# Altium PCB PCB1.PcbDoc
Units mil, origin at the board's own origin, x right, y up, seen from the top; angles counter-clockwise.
Board outline 794 x 1228 mil, 2 copper layers (Top Layer, Bottom Layer); 31 components, 47 nets, 231 pads, 76 vias.
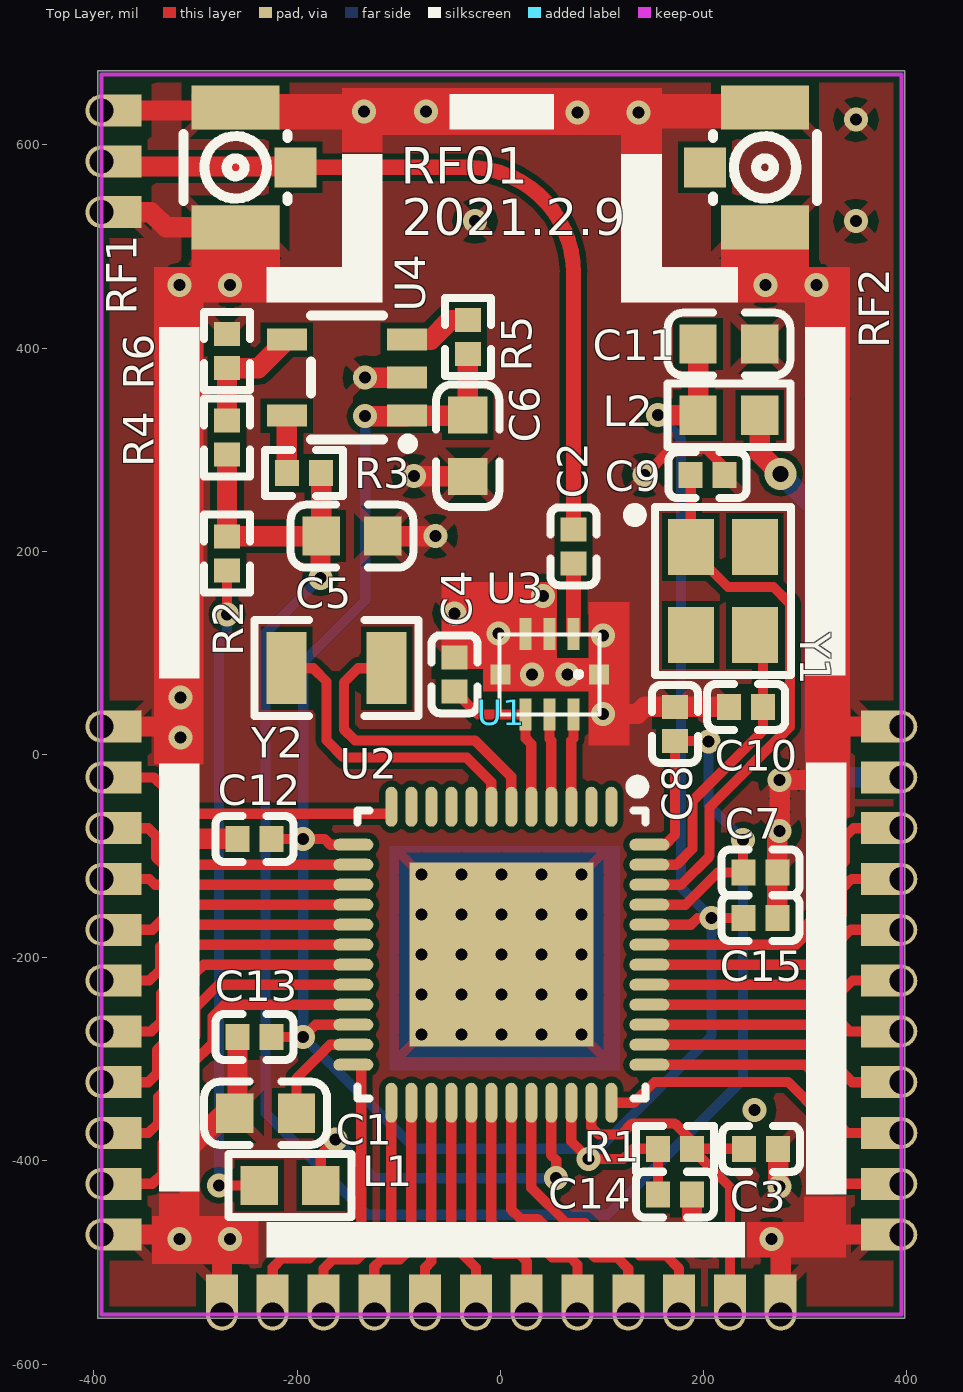
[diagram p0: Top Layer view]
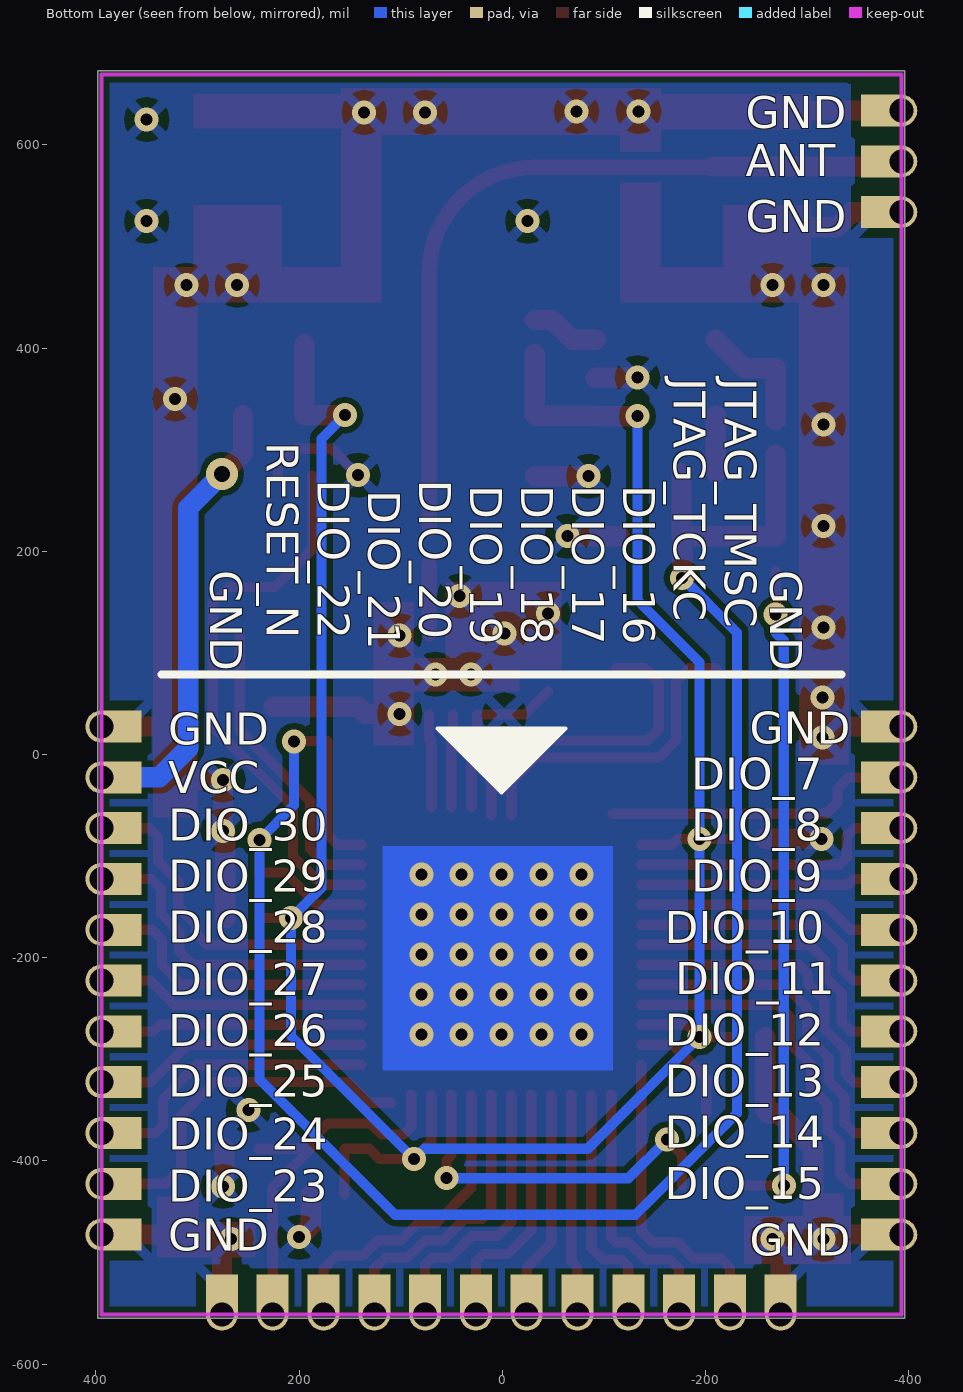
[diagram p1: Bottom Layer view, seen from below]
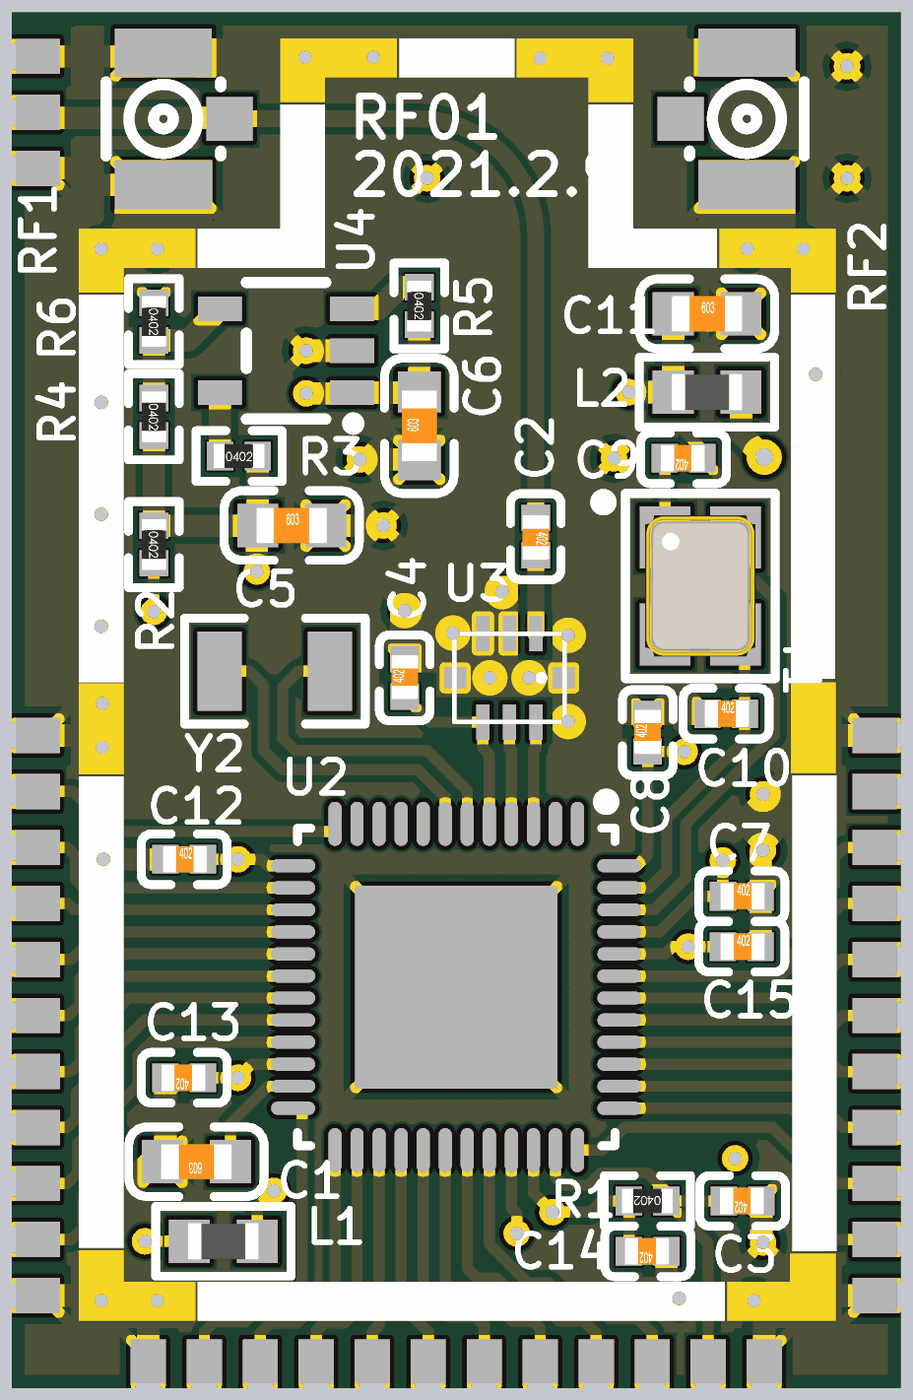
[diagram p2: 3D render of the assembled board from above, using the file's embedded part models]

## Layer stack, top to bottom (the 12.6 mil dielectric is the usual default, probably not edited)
Top Solder: solder mask 0.4, Solder Resist, Dk 3.5
Top Layer: signal copper 1.4
Dielectric 1: dielectric 12.6, FR-4, Dk 4.8
Bottom Layer: signal copper 1.4
Bottom Solder: solder mask 0.4, Solder Resist, Dk 3.5

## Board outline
-396,673 398,673 398,-555 -396,-555

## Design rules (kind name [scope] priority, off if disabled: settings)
Clearance [All] p1: gap=6
ComponentClearance [All] p1: gap=0 collisioncheckmode=3 verticalgap=0 showdistances=FALSE
PolygonConnect [All] p1: connectstyle=Relief reliefconductorwidth=10 reliefentries=4 polygonreliefangle="45 Angle" airgapwidth=10
RoutingVias [All] p1: holewidth=28 width=50 viastyle="Through Hole" minholewidth=1 minwidth=2 maxholewidth=28 maxwidth=50
SMDNeckDown [All] p1: percent=50.000
SolderMaskExpansion [All] p1: expansion=4
Width [All] p1: maxlimit=100 minlimit=10 preferedwidth=10 minimp=50.000000 maximp=50.000000 favimp=50.000000
29 further rules are at their usual default settings.

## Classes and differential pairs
component class Sheet2: U1

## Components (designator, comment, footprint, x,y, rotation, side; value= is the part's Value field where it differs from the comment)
C1 "1uF (105) 10% 50V" 0603_C -231,-353 r180 top
C2 "330pF (331) 5% 50V" 0402_C 72,205 r270 top
C3 "100nF (104) 10% 16V" 0402_C 256.73,-388 r180 top
C4 "330pF (331) 5% 50V" 0402_C -45,79 r90 top
C5 "22uF (226) 20% 6.3V" 0603_C -146,215 r0 top
C6 "1uF (105) 10% 50V" 0603_C -32,304 r90 top
C7 "100nF (104) 10% 16V" 0402_C 256,-116 r0 top
C8 "100nF (104) 10% 16V" 0402_C 172,30 r90 top
C9 "6.8pF (6R8) 0.25pF 50V" 0402_C 204,275 r180 top
C10 "6.8pF (6R8) 0.25pF 50V" 0402_C 242,47 r0 top
C11 "22uF (226) 20% 6.3V" 0603_C 225,404 r0 top
C12 "100nF (104) 10% 16V" 0402_C -242,-83 r0 top
C13 "100nF (104) 10% 16V" 0402_C -242,-278 r180 top
C14 "100nF (104) 10% 16V" 0402_C 172,-433 r180 top
C15 "100nF (104) 10% 16V" 0402_C 256,-161 r0 top
L1 "6.8uH ±10%" 0603_L -207,-424 r0 top
L2 "10uH ±10%" 0603_L 225,334 r180 top
R1 "100KΩ (1003) ±1%" 0402_R 171.73,-388 r180 top
R2 "0Ω (0R0) ±1%" 0402_R -269,198 r270 top
R3 "0Ω (0R0) ±1%" 0402_R -193,277 r0 top
R4 "22KΩ (2202) ±1%" 0402_R -269,312 r270 top
R5 "10KΩ (1002) ±1%" 0402_R -32,411 r270 top
R6 "20KΩ (2002) ±1%" 0402_R -269,397 r270 top
RF1 "KH-IPEX-K501-29" ANT-SMD_KH-IPEX-K501-29 -231,578 r270 top
RF2 "KH-IPEX-K501-29" ANT-SMD_KH-IPEX-K501-29 231,578 r90 top
U1 "E79-400DM2005S" E79-400DM2005S_V1.0_MODULE -16,0 r0 top locked
U2 "CC1352R1F3RGZR" QFN48 1,-197 r270 top locked
U3 "RFBLN2520090YC3T10" FILTER-SMD_8P-L2.5-W2.0-BL 48.5,79 r0 top locked
U4 "SGM2036-ADJYN5G/TR" SOT-23-5_L3.0-W1.7-P0.95-LS2.8-BR -151,371 r0 top
Y1 "48MHZ 20PF 10PPM" SMD-3225_4P 219,161 r270 top
Y2 "32.768KHz ±20ppm 12.5pF" "SMD-3215_2P FC - 135" -161,85 r0 top

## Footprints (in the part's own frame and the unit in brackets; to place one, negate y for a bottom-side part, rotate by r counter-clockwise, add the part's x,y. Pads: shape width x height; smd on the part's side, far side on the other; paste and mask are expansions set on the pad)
0402_C [mm]
  rect 0.6x0.65 smd mask+0.051: 1(-0.425,0) 2(0.425,0)
  silkscreen extent -0.97,-0.58 0.97,0.58, body extent -0.48,-0.3 0.52,0.3, height 0.2
0402_R [mm]
  rect 0.6x0.65 smd mask+0.051: 1(-0.425,0) 2(0.425,0)
  silkscreen extent -0.97,-0.58 0.97,0.58, body extent -0.57,-0.27 0.58,0.28, height 0.41
0603_C [mm]
  rect 0.93x0.98 smd: 1(-0.77,0) 2(0.77,0)
  silkscreen extent -1.53,-0.79 1.54,0.79, body extent -0.8,-0.4 0.8,0.4, height 0.3
0603_L [mm]
  rect 0.93x0.98 smd: 1(-0.77,0) 2(0.77,0)
  silkscreen extent -1.53,-0.79 1.54,0.79, body extent -0.82,-0.41 0.83,0.41, height 0.46
ANT-SMD_KH-IPEX-K501-29 [mm]
  rect 1.1x2.2 smd: 1(-1.5,-0.75) 3(1.5,-0.75)
  rect 1x1.05 smd: 2(0,0.75)
  silkscreen extent -0.84,-2.05 0.84,0.55
E79-400DM2005S_V1.0_MODULE [mm]
  round 0.8 hole 0.6: 1(-9.568,16.1) 2(-9.568,14.83) 3(-9.568,13.56) 4(-9.568,0.7) 5(-9.568,-0.57) 6(-9.568,-1.84) 7(-9.568,-3.11) 8(-9.568,-4.38) 9(-9.568,-5.65) 10(-9.568,-6.92) 11(-9.568,-8.19) 12(-9.568,-9.46) 13(-9.568,-10.73) 14(-9.568,-12) 15(-6.553,-14) 16(-5.283,-14) 17(-4.013,-14) 18(-2.743,-14) 19(-1.473,-14) 20(-0.203,-14) 21(1.067,-14) 22(2.337,-14) 23(3.607,-14) 24(4.877,-14) 25(6.147,-14) 26(7.417,-14) 27(10.432,-12) 28(10.432,-10.73) 29(10.432,-9.46) 30(10.432,-8.19) 31(10.432,-6.92) 32(10.432,-5.65) 33(10.432,-4.38) 34(10.432,-3.11) 35(10.432,-1.84) 36(10.432,-0.57) 37(10.432,0.7)
  rect 1x0.8 smd: 1(-9.06,16.1) 2(-9.06,14.83) 3(-9.06,13.56) 4(-9.06,0.7) 5(-9.06,-0.57) 6(-9.06,-1.84) 7(-9.06,-3.11) 8(-9.06,-4.38) 9(-9.06,-5.65) 10(-9.06,-6.92) 11(-9.06,-8.19) 12(-9.06,-9.46) 13(-9.06,-10.73) 14(-9.06,-12) 27(9.924,-12) 28(9.924,-10.73) 29(9.924,-9.46) 30(9.924,-8.19) 31(9.924,-6.92) 32(9.924,-5.65) 33(9.924,-4.38) 34(9.924,-3.11) 35(9.924,-1.84) 36(9.924,-0.57) 37(9.924,0.7)
  rect 1x0.8 smd far side: 1(-9.06,16.1) 2(-9.06,14.83) 3(-9.06,13.56) 4(-9.06,0.7) 5(-9.06,-0.57) 6(-9.06,-1.84) 7(-9.06,-3.11) 8(-9.06,-4.38) 9(-9.06,-5.65) 10(-9.06,-6.92) 11(-9.06,-8.19) 12(-9.06,-9.46) 13(-9.06,-10.73) 14(-9.06,-12) 27(9.924,-12) 28(9.924,-10.73) 29(9.924,-9.46) 30(9.924,-8.19) 31(9.924,-6.92) 32(9.924,-5.65) 33(9.924,-4.38) 34(9.924,-3.11) 35(9.924,-1.84) 36(9.924,-0.57) 37(9.924,0.7)
  rect 0.8x1 smd: 15(-6.553,-13.492) 16(-5.283,-13.492) 17(-4.013,-13.492) 18(-2.743,-13.492) 19(-1.473,-13.492) 20(-0.203,-13.492) 21(1.067,-13.492) 22(2.337,-13.492) 23(3.607,-13.492) 24(4.877,-13.492) 25(6.147,-13.492) 26(7.417,-13.492)
  rect 0.8x1 smd far side: 15(-6.553,-13.492) 16(-5.283,-13.492) 17(-4.013,-13.492) 18(-2.743,-13.492) 19(-1.473,-13.492) 20(-0.203,-13.492) 21(1.067,-13.492) 22(2.337,-13.492) 23(3.607,-13.492) 24(4.877,-13.492) 25(6.147,-13.492) 26(7.417,-13.492)
  Keep-Out Layer lines w0.1: -9.568,-14 -9.568,17 10.432,17 10.432,-14 -9.568,-14
FILTER-SMD_8P-L2.5-W2.0-BL [mm]
  rect 0.3x0.8 smd: 1(0.6,1.006) 2(0,1.006) 3(-0.6,1.006) 5(-0.6,-1.006) 6(0,-1.006) 7(0.6,-1.006)
  rect 0.5x0.5 smd: 4(-1.233,0) 8(1.233,0)
  silkscreen extent -1.25,-1 1.25,1
QFN48 [mm]
  rect 4.6x4.6 smd: 0(0,0)
  oval 1x0.3 smd: 1(-3.7,2.75) 2(-3.7,2.25) 3(-3.7,1.75) 4(-3.7,1.25) 5(-3.7,0.75) 6(-3.7,0.25) 7(-3.7,-0.25) 8(-3.7,-0.75) 9(-3.7,-1.25) 10(-3.7,-1.75) 11(-3.7,-2.25) 12(-3.7,-2.75) 25(3.7,-2.75) 26(3.7,-2.25) 27(3.7,-1.75) 28(3.7,-1.25) 29(3.7,-0.75) 30(3.7,-0.25) 31(3.7,0.25) 32(3.7,0.75) 33(3.7,1.25) 34(3.7,1.75) 35(3.7,2.25) 36(3.7,2.75)
  oval 0.3x1 smd: 13(-2.75,-3.7) 14(-2.25,-3.7) 15(-1.75,-3.7) 16(-1.25,-3.7) 17(-0.75,-3.7) 18(-0.25,-3.7) 19(0.25,-3.7) 20(0.75,-3.7) 21(1.25,-3.7) 22(1.75,-3.7) 23(2.25,-3.7) 24(2.75,-3.7) 37(2.75,3.7) 38(2.25,3.7) 39(1.75,3.7) 40(1.25,3.7) 41(0.75,3.7) 42(0.25,3.7) 43(-0.25,3.7) 44(-0.75,3.7) 45(-1.25,3.7) 46(-1.75,3.7) 47(-2.25,3.7) 48(-2.75,3.7)
  silkscreen extent -4.35,-3.6 3.6,3.6
"SMD-3215_2P FC - 135" [mm]
  rect 1x1.8 smd: 1(-1.25,0) 2(1.25,0)
  silkscreen extent -2.05,-1.2 2.05,1.2
SMD-3225_4P [mm]
  rect 1.4x1.15 smd: 1(-1.1,-0.8) 2(1.1,-0.8) 3(1.1,0.8) 4(-1.1,0.8)
  silkscreen extent -2.1,-2.35 2.1,1.7, body extent -1.6,-1.25 1.6,1.25, height 0.61
SOT-23-5_L3.0-W1.7-P0.95-LS2.8-BR [mm]
  rect 1x0.55 smd: 1(1.5,-0.95) 2(1.5,0) 3(1.5,0.95) 4(-1.5,0.95) 5(-1.5,-0.95)
  silkscreen extent -0.9,-1.78 1.65,1.55

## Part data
C1 C6: library part "0603 1uF (105) 10% 50V", "贴片电容"
C2 C4: library part "0402 330pF (331) 5% 50V", "贴片电容"
C3 C7 C8 C12 C13 C14 C15: library part "0402 100nF (104) 10% 16V", "贴片电容"
C5 C11: library part "0603 22uF (226) 20% 6.3V", "贴片电容"
C9 C10: library part "0402 6.8pF (6R8) 0.25pF 50V", "贴片电容"
L1: library part "0603 4.7uH 10%", "贴片电感"
L2: library part "0603 10uH 10%", "贴片电感"
R1: library part "0402 100KΩ (1003) 1%", "贴片电阻"
R2 R3: library part "0402 0Ω (0R0) 1%", "贴片电阻"
R4: library part "0402 22KΩ (2202) 1%", "贴片电阻"
R5: library part "0402 10KΩ (1002) 1%", "贴片电阻"
R6: library part "0402 20KΩ (2002) 1%", "贴片电阻"
Y1: library part "SMD-3225_4P  12MHZ 20PF 10PPM", "贴片晶振"
Y2: library part "SMD-3215_2P 32.768KHz 20ppm 12.5pF", "贴片晶振"

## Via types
v1: diameter 23.62, hole 11.81, Top Layer to Bottom Layer, 75 vias
v2: diameter 31.5, hole 15.75, Top Layer to Bottom Layer, 1 vias

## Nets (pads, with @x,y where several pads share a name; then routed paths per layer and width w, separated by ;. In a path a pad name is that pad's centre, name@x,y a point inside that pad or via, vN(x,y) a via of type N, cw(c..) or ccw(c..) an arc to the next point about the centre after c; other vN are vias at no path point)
2.4G_ANT: RF2.2
3V3: L2.1 U1.36 | length 427.7
  Top Layer w20: L2.1 255.31,296.69 v2(276,276)
  Bottom Layer w20: v2(276,276) 309,243 309,6 337.44,-22.44 U1.36@374.7,-22.44
433M_ANT: C2.1 RF1.2 U1.2 | length 750.5
  Top Layer w15: RF1.2 -32,578 cw(c-32,474) 72,474 C2.1
  Top Layer w20: U1.2@-372.7,578.86 RF1.2@-207.33,578.86
DIO7: U1.5 U2.12 | length 287.2
  Top Layer w10: U1.5@-372.7,-22.44 -341,-22.44 -330,-33.44 -330,-47 -318.8,-58.2 U2.12@-108.27,-58.2
DIO8: U1.6 U2.14 | length 263.1
  Top Layer w10: U1.6@-372.7,-72.44 -346.56,-72.44 -339,-80 -339,-101 -331.58,-108.42 U2.14@-136.79,-108.42
DIO9: U1.7 U2.15 | length 238.2
  Top Layer w10: U1.7@-372.7,-122.44 -345.56,-122.44 -339.9,-128.1 U2.15@-136.79,-128.1
DIO10: U1.8 U2.16 | length 246.1
  Top Layer w10: U1.8@-372.7,-172.44 -342.44,-172.44 -317.79,-147.79 U2.16@-136.79,-147.79
DIO11: U1.9 U2.17 | length 272.1
  Top Layer w10: U1.9@-372.7,-222.44 -345.44,-222.44 -335,-212 -335,-189.04 -313.43,-167.47 U2.17@-136.79,-167.47
DIO12: U1.10 U2.18 | length 297
  Top Layer w10: U1.10@-372.7,-272.44 -343.44,-272.44 -334,-263 -334,-235.04 -318,-219.04 -318,-203 -302.16,-187.16 U2.18@-136.79,-187.16
DIO13: U1.11 U2.19 | length 319.5
  Top Layer w10: U1.11@-372.7,-322.44 -346.44,-322.44 -338,-314 -338,-291.04 -317,-270.04 -317,-242.08 -301,-226.08 -301,-216 -291.84,-206.84 U2.19@-136.79,-206.84
DIO14: U1.12 U2.20 | length 341.4
  Top Layer w10: U1.12@-372.7,-372.44 -346.4,-372.44 -337,-363.04 -337,-337.04 -321,-321.04 -321,-298.08 -300,-277.08 -300,-249.12 -277.4,-226.53 U2.20@-136.79,-226.53
DIO15: U1.13 U2.21 | length 370.4
  Top Layer w10: U1.13@-372.7,-422.44 -342.44,-422.44 -332.46,-412.46 -332.46,-382.54 -320,-370.08 -320,-344.08 -304,-328.08 -304,-305.12 -283,-284.12 -283,-258 -271.21,-246.21 U2.21@-136.79,-246.21
DIO16: U1.18 U2.26 | length 222
  Top Layer w10: U1.18@-124,-531.18 -124,-504 -117,-497 -99,-497 -87.58,-485.58 U2.26@-87.58,-334.79
DIO17: U1.19 U2.27 | length 198.9
  Top Layer w10: U1.19@-74,-531.18 -74,-505 -67.9,-498.9 U2.27@-67.9,-334.79
DIO18: U1.20 U2.28 | length 206.4
  Top Layer w10: U2.28@-48.21,-334.79 -48.21,-480.79 -24,-505 U1.20@-24,-531.18
DIO19: U1.21 U2.29 | length 233
  Top Layer w10: U2.29@-28.53,-334.79 -28.53,-468.47 -5.5,-491.5 18.5,-491.5 26,-499 U1.21@26,-531.18
DIO20: U1.22 U2.30 | length 256.7
  Top Layer w10: U2.30@-8.84,-334.79 -8.84,-460.16 5,-474 30.04,-474 51.04,-495 69,-495 76,-502 U1.22@76,-531.18
DIO21: U1.23 U2.31 | length 277.5
  Top Layer w10: U2.31@10.84,-334.79 10.84,-447.84 20,-457 37.08,-457 58.08,-478 76.04,-478 93.04,-495 115,-495 126,-506 U1.23@126,-531.18
DIO22: U1.24 U2.32 | length 295.2
  Top Layer w10: U2.32@30.53,-334.79 30.53,-426.4 65.12,-461 83.08,-461 100.08,-478 122.04,-478 137.04,-493 163,-493 176,-506 U1.24@176,-531.18
DIO23: U1.28 U2.36 | length 345.8
  Top Layer w10: U2.36 131.33,-342.67 151.73,-322.27 283.27,-322.27 316,-355 316,-407 331.44,-422.44 U1.28@374.7,-422.44
DIO24: U1.29 U2.37 | length 279
  Top Layer w10: U2.37@138.8,-305.27 300.27,-305.27 334,-339 334,-365 341.44,-372.44 U1.29@374.7,-372.44
DIO25: U1.30 U2.38 | length 251.2
  Top Layer w10: U2.38@138.8,-285.58 309.58,-285.58 346.44,-322.44 U1.30@374.7,-322.44
DIO26: U1.31 U2.39 | length 238.6
  Top Layer w10: U2.39@138.8,-265.9 336.9,-265.9 343.44,-272.44 U1.31@374.7,-272.44
DIO27: U1.32 U2.40 | length 245.8
  Top Layer w10: U2.40@138.8,-246.21 322.79,-246.21 346.56,-222.44 U1.32@374.7,-222.44
DIO28: U1.33 U2.41 | length 273
  Top Layer w10: U2.41@138.8,-226.53 315.47,-226.53 335,-207 335,-182 344.56,-172.44 U1.33@374.7,-172.44
DIO29: U1.34 U2.42 | length 296.6
  Top Layer w10: U2.42@138.8,-206.84 305.16,-206.84 318,-194 318,-174.96 336,-156.96 336,-132 345.56,-122.44 U1.34@374.7,-122.44
DIO30: U1.35 U2.43 | length 317.4
  Top Layer w10: U2.43@138.8,-187.16 290.84,-187.16 301,-177 301,-167.92 319,-149.92 319,-124.96 339,-104.96 339,-81 347.56,-72.44 U1.35@374.7,-72.44
GND: C1.2 C3.1 C4.2 C5.2 C6.1 C7.2 C8.2 C9.1 C10.1 C11.2 C12.1 C13.2 C14.1 C15.2 R6.1 RF1.1 RF1.3 RF2.1 RF2.3 U1.1 U1.3 U1.4 U1.14 U1.15 U1.26 U1.27 U1.37 U2.0 U3.2 U3.3 U3.4 U3.8 U4.2 | length 1463.1
  Top Layer w10: v1(142,275) 168,301 202.51,301 220.73,282.78 C9.1
  Top Layer w20: U1.14@-372.7,-472.44 -302.56,-472.44 ; U1.4@-372.7,27.56 -325.56,27.56 ; U1.3@-372.7,533.86 -343.86,533.86 -328.95,518.94 RF1.3 ; U1.1@-372.7,633.86 RF1.1@-263.72,633.86 ; v1(-314,-83) C12.1 ; -306,-445 -306,-387 -272,-353 C1.2 ; U1.15@-274,-531.18 v1@-274,-475 ; C1.2@-258.73,-350.42 C13.2 ; v1(-133,371) U4.2 ; C5.2 v1(-64,215) ; v1(-85,274) C6.1@-32.32,274 ; v1(101,40) 135,40 142,47 C10.1 ; C14.1 188.73,-463.73 v1(200,-475) ; C15.2 C7.2 v1@272.73,-77.27 ; v1@273.46,-423.46 C3.1 ; v1(275,-75) v1(275,-25) 325,-25 ; U1.26@276,-531.18 276,-486 ; 300.56,-472.44 U1.27@374.7,-472.44 ; 319.44,27.56 U1.37@374.7,27.56
  other v1: -316,-477 -266,-477 267,-477 275,-425 250,-350 -77.74,-275.74 -38.37,-275.74 1,-275.74 40.37,-275.74 79.74,-275.74 -77.74,-236.37 -38.37,-236.37 1,-236.37 40.37,-236.37 79.74,-236.37 -77.74,-197 -38.37,-197 1,-197 40.37,-197 79.74,-197 -77.74,-157.63 -38.37,-157.63 1,-157.63 40.37,-157.63 79.74,-157.63 -77.74,-118.26 -38.37,-118.26 1,-118.26 40.37,-118.26 79.74,-118.26 -315,17 -315,56 31,79 66,79 101,117 -2,119 -316,125 -45,139 42,156 -316,225 -316,325 322,350 -316,462 -266,462 261,462 311,462 -25,525 350,525 350,625 76,632 136,632 -134,633 -73,633
NetC1_1: C1.1 U2.23 | length 111.9
  Top Layer w10: C1.1 -200.68,-318.68 -167.58,-285.58 U2.23@-136.79,-285.58
NetC2_2: C2.2 U3.1 | length 69.5
  Top Layer w15: U3.1 C2.2@72.12,188.15
NetC4_1: C4.1 U2.5 U3.5 | length 172.4
  Top Layer w10: C4.1 -22.12,39.39 U3.5 24.88,16.12 30.53,10.47 U2.5
NetC9_2: C9.2 U2.46 Y1.1 | length 553
  Top Layer w10: U2.46@138.8,-128.1 177.86,-128.1 206,-99.96 206,-51.63 285,27.37 285,148.94 268.94,165 224.05,165 187.5,201.55 Y1.1 C9.2@187.5,274.76
NetC10_2: C10.2 U2.47 Y1.3 | length 296
  Top Layer w10: U2.47@138.8,-108.42 173.5,-108.42 189,-92.92 189,-46 258.5,23.5 Y1.3@258.5,117.69
NetL1_1: L1.1 R2.2 | length 648.3
  Top Layer w10: v1(-277,-424) L1.1 ; v1(-269,138) R2.2
  Bottom Layer w10: v1(-277,-424) -277,112 -269,120 v1(-269,138)
NetL1_2: L1.2 U2.33 | length 368
  Top Layer w10: L1.2 -176.68,-393.68 v1(-162,-379) ; U2.33@50.21,-334.79 50.21,-394.21 55,-399 v1(55,-417)
  Bottom Layer w10: v1(-162,-379) -124,-417 v1(55,-417)
NetR3_1: R3.1 U4.5 | length 56.3
  Top Layer w20: R3.1@-210.06,277.33 U4.5
NetR4_1: R4.1 R6.2 U4.4 | length 122.1
  Top Layer w20: R4.1 R6.2 -238.19,380.27 U4.4
NetR5_1: R5.1 U4.3 | length 68
  Top Layer w20: U4.3 -68.6,408.4 -49.27,427.73 R5.1
NetU2_3: U2.3 U3.7 | length 88.5
  Top Layer w10: U2.3 69.9,13.9 ; 72.12,16.12 U3.7
NetU2_4: U2.4 U3.6 | length 91.4
  Top Layer w10: U3.6 48.5,15.5 50.21,13.79 U2.4
NetU2_6: U2.6 Y2.2 | length 315.6
  Top Layer w10: Y2.2 -140,85 -154,71 -154,25 -143,14 -25,14 10.84,-21.84 U2.6@10.84,-59.2
NetU2_7: U2.7 Y2.1 | length 313.8
  Top Layer w10: Y2.1 -184,85 -171,72 -171,14 -154,-3 -33,-3 -8.84,-27.16 U2.7@-8.84,-59.2
RESET: C3.2 R1.1 U1.25 U2.35 | length 355.6
  Top Layer w10: U2.35@89.58,-334.79 U2.35 89.58,-366.58 97,-374 119,-374 130,-363 171.58,-363 R1.1@188.46,-379.89 ; U1.25@226,-531.18 226,-425.54 R1.1 C3.2
TCKC: U1.17 U2.25 | length 245.1
  Top Layer w10: U1.17@-174,-531.18 -174,-506 -165,-497 -141.04,-497 -124.04,-480 -112,-480 -107.27,-475.27 U2.25@-107.27,-334.79
TMSC: U1.16 U2.24 | length 291.9
  Top Layer w10: U1.16@-224,-531.18 -224,-505 -215,-496 -188.04,-496 -172.04,-480 -148.08,-480 -136.79,-468.71 U2.24@-136.79,-305.27
VDDR: C5.1 C7.1 C8.1 R2.1 R3.2 R4.2 U2.45 U2.48 | length 2046
  Top Layer w10: U2.45@138.8,-147.79 182.21,-147.79 214,-116 C7.1 ; U2.48@138.8,-88.73 162.27,-88.73 172,-79 C8.1 v1@204.73,13.27 ; C7.1@239,-115.73 v1(239,-84)
  Top Layer w20: R4.2 R2.1 -176.58,214.73 C5.1 C5.1 R3.2 ; v1(-177,174) C5.1@-177,214.32
  Bottom Layer w10: v1(-177,174) -231,120 -231,-353 -131,-453 105.67,-453 239,-319.67 v1(239,-84) 205,-50 v1(205,13)
VDDS: C6.2 C11.1 C12.2 C13.1 C14.2 C15.1 L2.2 R1.2 R5.2 U2.13 U2.22 U2.34 U2.44 U4.1 | length 2516
  Top Layer w10: C13.1 v1(-194,-278) -181.9,-265.9 U2.22@-136.79,-265.9 ; C12.2 v1(-194,-83) -173,-83 -167.27,-88.73 U2.13@-136.79,-88.73 ; U2.34@69.9,-334.79 U2.34 69.9,-380.9 v1(87,-398) 121,-398 131,-388 R1.2 ; U2.44@138.8,-167.47 187.53,-167.47 194,-161 v1(208,-161) C15.1 ; C14.2 R1.2@155.27,-388.27
  Top Layer w20: v1(-133,333) U4.1@-92.55,333 ; U4.1 -32.72,333.6 C6.2 R5.2 ; v1(155,334) L2.2 C11.1
  Bottom Layer w10: v1(-133,333) -133,152 -194,91 v1(-194,-83) v1(-194,-278) -84,-388 77,-388 v1(87,-398) 208,-277 v1(208,-161) 178,-131 178,311 v1(155,334)
pads on no net: U2.1 U2.2 U2.8 U2.9 U2.10 U2.11 Y1.2 Y1.4

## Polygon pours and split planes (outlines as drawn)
GND on Bottom Layer "Bottom Layer-No Net" (solid, remove dead copper, pour order 4): -395,672 397,672 397,-554 -395,-554
GND on Top Layer "Bottom Layer-No Net" (solid, remove dead copper, pour order 6): -395,672 397,672 397,-554 -395,-554

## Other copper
Top Layer:
  rectangle net GND: 87,9 127,150
  rectangle net GND: -58,84 6,170
  rectangle net GND: -17,62 56,170
  rectangle net GND: -17,62 110,95
  rectangle net GND: 217,474 304,541
  rectangle net GND: 159,616 304,650
  rectangle net GND: -304,458 -217,541
  rectangle net GND: -304,615 -147,650
  rectangle net GND: 300,-62 344,480
  region net GND: -116,445 -116,563 -156,563 -156,445
  rectangle net GND: 119,445 340,480
  region net GND: -292,-10 -292,480 -341,480 -341,-10
  rectangle net GND: -336,445 -116,480
  rectangle net GND: 119,445 159,650
  rectangle net GND: -156,610 159,656
  rectangle net GND: 243,-495 340,-460
  rectangle net GND: -156,593 -116,650
  rectangle net GND: 299,-495 340,-435
  rectangle net GND: -343.02,-501.5 -238,-454
  rectangle net GND: -336,-495 -296,-432
Bottom Layer:
  rectangle net GND: -109,-311 118,-90

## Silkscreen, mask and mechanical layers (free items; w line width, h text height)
Top Overlay:
  rectangle: 301,-433 340.58,-8
  rectangle: -336,-430 -296,-9
  rectangle: 119,445 234,480
  rectangle: 119,445 159,591
  rectangle: -230,-495 241,-460
  rectangle: 300,78 339.58,421
  rectangle: -50,615 53,650
  rectangle: -156,445 -116,591
  rectangle: -230,445 -116,480
  rectangle: -336,75 -296,421
  text "RF01" at -98,562 h36
  text "2021.2.9" at -97,511 h36
Top Solder:
  rectangle: 300,-6 340,75
  rectangle: -336,-7 -296,74
  rectangle: 300,423 340,480
  rectangle: 236,445 340,480
  rectangle: -336,445 -232,480
  rectangle: -336,423 -296,480
  rectangle: 119,593 159,650
  rectangle: 55,615 159,650
  rectangle: -156,615 -52,650
  rectangle: -156,593 -116,650
  rectangle: 299,-495 340,-435
  rectangle: 243,-495 340,-460
  rectangle: -336,-495 -232,-460
  rectangle: -336,-495 -296,-432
